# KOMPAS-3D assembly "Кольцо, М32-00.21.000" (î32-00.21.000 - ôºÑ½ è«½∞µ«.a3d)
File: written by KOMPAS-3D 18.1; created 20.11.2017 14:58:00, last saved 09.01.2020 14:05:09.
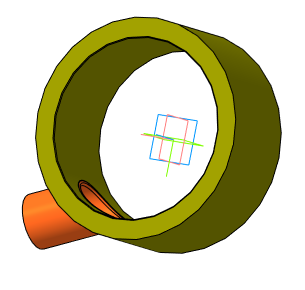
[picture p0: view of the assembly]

Document properties: Автор: Милов; Организация: Милов; Полное имя файла: D:\Magna\Магна Ins\Магна ins 32\Для Караби\М32-00.21.000 - Узел Кольцо.a3d

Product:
- Part/product: Кольцо  | designation М32-00.21.000  | pos. 0
    Масса: 1.28716
    Раздел спецификации: Сборочные единицы
    Форматы листов документа: A3
    source file: М32-00.21.000 - Кольцо.cdw
  - Component [detail]: Кольцо  | designation М40-00.21.001  | pos. 0  | Материал: Полипропилен  ГОСТ 26996-86 (density 900 kg/m3); Масса: 1.59002; Раздел спецификации: Детали; Форматы листов документа: A3; source file: ..\Магна ins 40\3Д\М40-00.21.001 - Кольцо.cdw, М32-00.21.001 - Кольцо.m3d
  - Component [detail]: Труба 63 PN10 S=5,8 FV PPR ф. FV PLAST  | designation 1003  | pos. 0  | Материал: Полипропилен  ГОСТ 26996-86 (density 900 kg/m3); Масса: 0.152669; Раздел спецификации: Прочие изделия; Примечание: м
  - Component [detail]: Деталь  | pos. 4  | Масса: 0.0160222; Раздел спецификации: Детали; source file: ..\Стержень для позиционирования корпуса.m3d
- Part/product: Узел Кольцо  | designation М32-00.21.000
    Масса: 1.30083
    source file: М32-00.21.000 - Кольцо.cdw, М32-00.21.000-01 - Кольцо.cdw
  - Component [detail]: Кольцо  | designation М32-00.21.001  | pos. 10  | Материал: Полипропилен  ГОСТ 26996-86 (density 900 kg/m3); Масса: 1.66598; Раздел спецификации: Детали; Форматы листов документа: A3; source file: М32-00.21.001 - Кольцо.cdw, М32-00.21.001 - Кольцо.m3d
  - Component [detail]: Труба 63 PN10 S=5,8 FV PPR ф. FV PLAST  | pos. 9  | Материал: Полипропилен  ГОСТ 26996-86 (density 900 kg/m3); Масса: 0.0740283; Раздел спецификации: Прочие изделия; Примечание: м; source file: ..\..\..\..\1 ПКИ 3D\Полипропиленовые фитинги, трубы\Трубы\Труба 63 PN10 S=5,8 FV PPR ф. FV PLAST.m3d
- Part/product: Кольцо  | designation М32-00.21.000
    Масса: 1.60884
  - Component [detail]: Кольцо  | designation М32-00.21.001  | pos. 8  | Материал: Полипропилен  ГОСТ 26996-86 (density 900 kg/m3); Масса: 1.5289; Раздел спецификации: Детали; source file: М32-00.21.001 - Кольцо.cdw, М32-00.21.001 - Кольцо.m3d
  - Component [detail]: Труба 63 PN10 S=5,8 FV PPR ф. FV PLAST  | pos. 7  | Материал: Полипропилен  ГОСТ 26996-86 (density 900 kg/m3); Масса: 0.0799362; Раздел спецификации: Прочие изделия; Примечание: м; source file: ..\..\..\..\1 ПКИ 3D\Полипропиленовые фитинги, трубы\Трубы\Труба 63 PN10 S=5,8 FV PPR ф. FV PLAST.m3d

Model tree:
1. Эскиз:1  (with: Операция выдавливания:6)
2. Вырезать элемент выдавливания:1
     Расстояние 1 = 110
3. Фаска:1  (with: Вырезать элемент выдавливания:1)
     Угол = 45; Длина 1 = 1; Длина 2 = 1
4. Скругление:1  (with: Вырезать элемент выдавливания:1, Операция выдавливания:1, Вырезать элемент выдавливания:4, Плоскость под углом:4)  (labels: Полипропилен  ГОСТ 26996-86)
     Радиус = 2; Расстояние = 46; Угол = 90
5. Эскиз:2  (with: Операция выдавливания:6, Вырезать элемент выдавливания:1)
6. Вырезать элемент выдавливания:2
     Расстояние 1 = 25
7. Условное изображение резьбы:5  (with: Вырезать элемент выдавливания:2)  (labels: M225x4; cil0_24705-2004 fine)
     Длина резьбы = 25; Шаг резьбы = 4; Номинальный диаметр резьбы = 225
8. Подгонка:2  (with: Вырезать элемент выдавливания:2)
9. Эскиз:3  (with: Вырезать элемент выдавливания:2)
10. Вырезать элемент выдавливания:3  (with: Операция выдавливания:1, Вырезать элемент выдавливания:4, Плоскость под углом:4)  (labels: Полипропилен  ГОСТ 26996-86)
     Расстояние 2 = 3; Расстояние = 46; Угол = 90
11. Эскиз:5  (with: Вырезать элемент выдавливания:15)
12. Эскиз:6
13. Эскиз:8  (with: Операция выдавливания:1)
14. Эскиз:10  (with: Вырезать элемент выдавливания:2)
15. Эскиз:11  (with: Вырезать элемент выдавливания:2)
16. Элемент выдавливания:1
     Расстояние 2 = 3
17. Условное изображение резьбы:8  (with: Вырезать элемент выдавливания:2, Элемент выдавливания:1)  (labels: M225x4; cil0_24705-2004 fine)
     Длина резьбы = 19; Шаг резьбы = 4; Номинальный диаметр резьбы = 225
18. Подгонка:1  (with: Вырезать элемент выдавливания:2, Операция выдавливания:1, Изменение положения:3)  (labels: Полипропилен  ГОСТ 26996-86)
     Ориентация = 2

Referenced files in D:\Magna\Магна Ins\Магна ins 32\Для Караби\: М32-00.21.001 - Кольцо.m3d, М32-00.21.001 - Кольцо.cdw
Referenced files in D:\Magna\Магна Ins\Магна ins 32\Для Караби\..\Магна ins 40\3Д\: М40-00.21.001 - Кольцо.cdw
Referenced files in D:\Magna\Магна Ins\Магна ins 32\: Стержень для позиционирования корпуса.m3d, М32-00.21.000 - Кольцо.cdw, М32-00.21.001 - Кольцо.m3d
Referenced files in D:\1 ПКИ 3D\Полипропиленовые фитинги, трубы\Трубы\: Труба 63 PN10 S=5,8 FV PPR ф. FV PLAST.m3d
Referenced files in D:\Magna\Магна Ins\Магна ins 40\3Д\: М40-00.30.000 - Корпус.a3d
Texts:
  Точка начала. Х
  Точка начала. Y
  Точка начала. Z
